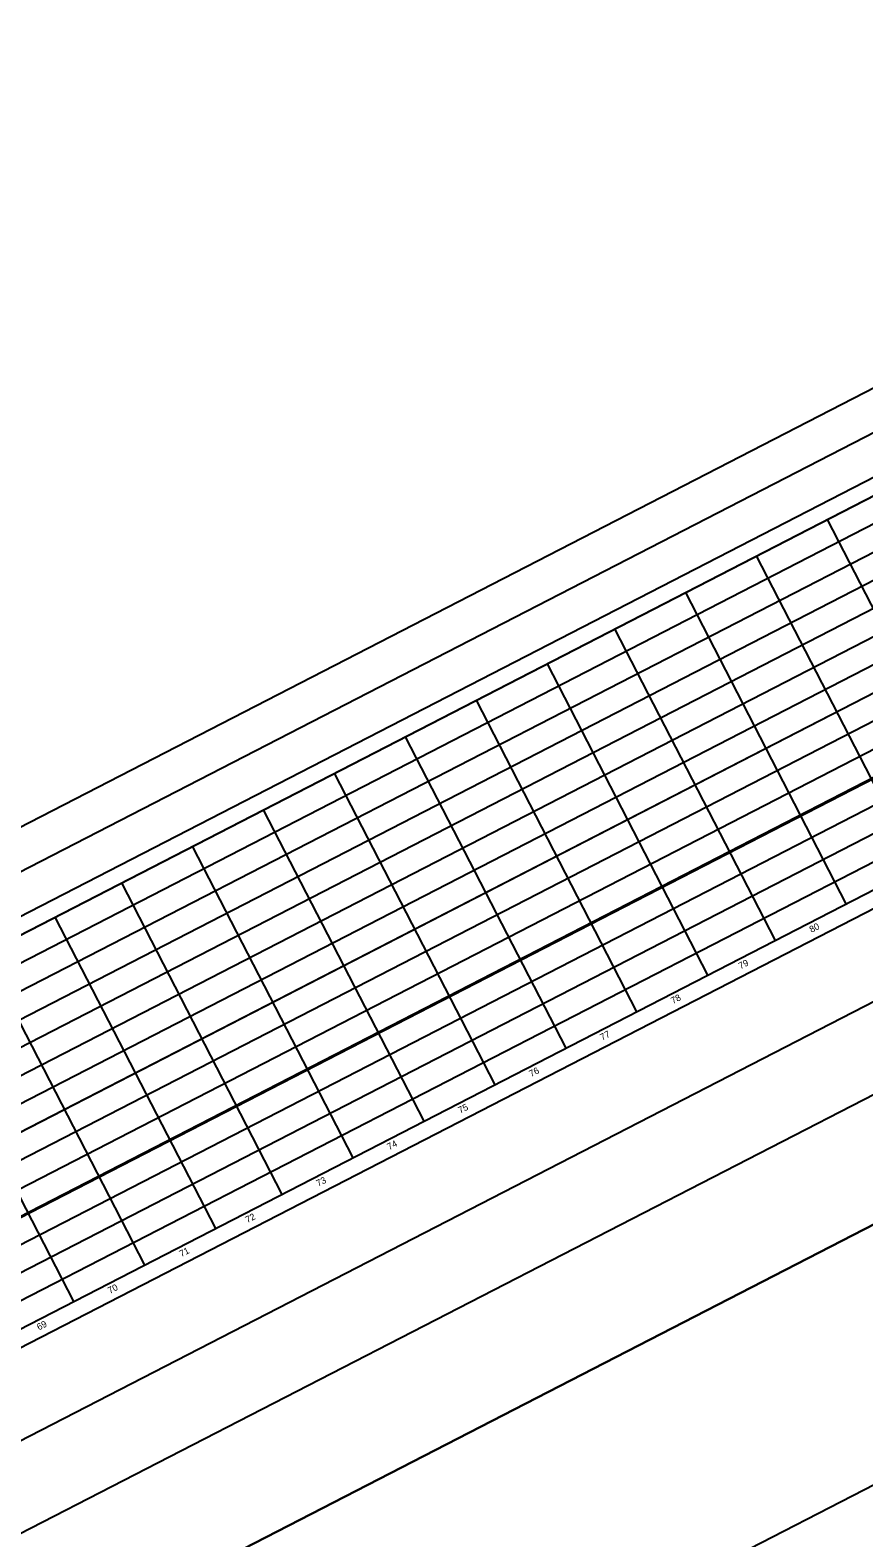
# Model space of a CAD drawing. Extents: x -886320 to -884760, y -1024172 to -1023483.
# Drawn here: x -885274.6 to -885148.6, y -1023827.5 to -1023599.4 of the extents above; entities that cross this region are included whole.
import ezdxf

# ---------------------------------------------------------------- set-up
doc = ezdxf.new("R2010")
doc.units = 0
for name, color, linetype in [('AGA__Netisknout', 7, 'Continuous'), ('Stavajici_betonova_draha', 7, 'Continuous'), ('Stavajici_betonova_draha_osa', 7, 'Continuous'), ('Stavajici_betonova_draha_Popis desky', 7, 'Continuous'), ('Stavajici_betonova_draha_Spára', 7, 'Continuous'), ('Stavajici_drahovy_system', 7, 'Continuous'), ('Stavajici_drahovy_system_osy', 7, 'Continuous'), ('Stavajici_drahovy_system_RWY_strip', 7, 'Continuous'), ('Stavajici_drahovy_system_TWY', 7, 'Continuous'), ('Stavajici_drahovy_system_TWY_osy', 7, 'Continuous')]:
    doc.layers.add(name, color=color, linetype=linetype)

msp = doc.modelspace()

# ---------------------------------------------------------------- linework, layer by layer
at = {"layer": 'AGA__Netisknout'}
msp.add_line((-886017.78, -1024147.99), (-884773.13, -1023507.02), dxfattribs=at)
at = {"layer": 'Stavajici_betonova_draha'}
for p, q in [((-886029.69, -1024124.32), (-884785.04, -1023483.35)), ((-886029.69, -1024124.32), (-884785.04, -1023483.35)), ((-886005.42, -1024171.44), (-884760.77, -1023530.47)), ((-886005.42, -1024171.44), (-884760.77, -1023530.47))]:
    msp.add_line(p, q, dxfattribs=at)
at = {"layer": 'Stavajici_betonova_draha_osa'}
msp.add_line((-886017.55, -1024147.88), (-884772.9, -1023506.91), dxfattribs=at)
at = {"layer": 'Stavajici_betonova_draha_Spára'}
for p, q in [((-886029.91, -1024124.43), (-884785.26, -1023483.46)), ((-886028.18, -1024127.8), (-884783.53, -1023486.82)), ((-886026.44, -1024131.16), (-884781.79, -1023490.19)), ((-886024.71, -1024134.53), (-884780.06, -1023493.56)), ((-886022.98, -1024137.89), (-884778.33, -1023496.92)), ((-886021.24, -1024141.26), (-884776.59, -1023500.29)), ((-886019.51, -1024144.63), (-884774.86, -1023503.65)), ((-886016.04, -1024151.36), (-884771.39, -1023510.39)), ((-886014.31, -1024154.72), (-884769.66, -1023513.75)), ((-886012.58, -1024158.09), (-884767.93, -1023517.12)), ((-886010.84, -1024161.46), (-884766.19, -1023520.48)), ((-886009.11, -1024164.82), (-884764.46, -1023523.85)), ((-886007.38, -1024168.19), (-884762.73, -1023527.21)), ((-886005.64, -1024171.55), (-884760.99, -1023530.58)), ((-885154.11, -1023673.41), (-885129.84, -1023720.53)), ((-885164.82, -1023678.92), (-885140.55, -1023726.05)), ((-885175.53, -1023684.44), (-885151.26, -1023731.56)), ((-885186.24, -1023689.96), (-885161.98, -1023737.08)), ((-885196.46, -1023695.22), (-885172.2, -1023742.34)), ((-885207.18, -1023700.74), (-885182.91, -1023747.86)), ((-885217.91, -1023706.26), (-885193.64, -1023753.39)), ((-885228.64, -1023711.79), (-885204.37, -1023758.91)), ((-885239.36, -1023717.31), (-885215.1, -1023764.44)), ((-885250.09, -1023722.84), (-885225.83, -1023769.96)), ((-885260.82, -1023728.37), (-885236.56, -1023775.49)), ((-885270.87, -1023733.54), (-885246.6, -1023780.66)), ((-885281.6, -1023739.06), (-885257.33, -1023786.19)), ((-885292.33, -1023744.59), (-885268.06, -1023791.71))]:
    msp.add_line(p, q, dxfattribs=at)
at = {"layer": 'Stavajici_drahovy_system'}
for p, q in [((-885721.56, -1024028.07), (-884864.53, -1023586.71)), ((-885726.12, -1024058.54), (-884837.08, -1023600.7)), ((-885744.78, -1024087.83), (-884802.4, -1023602.52)), ((-885728.75, -1024118.95), (-884786.38, -1023633.64))]:
    msp.add_line(p, q, dxfattribs=at)
at = {"layer": 'Stavajici_drahovy_system_osy'}
msp.add_line((-885731.84, -1024047.42), (-884842.81, -1023589.59), dxfattribs=at)
at = {"layer": 'Stavajici_drahovy_system_RWY_strip'}
for p, q in [((-885772.25, -1024034.49), (-884829.87, -1023549.18)), ((-884802.4, -1023602.52), (-885744.78, -1024087.83))]:
    msp.add_line(p, q, dxfattribs=at)
at = {"layer": 'Stavajici_drahovy_system_TWY'}
for p, q in [((-885887.27, -1024034.67), (-884885.91, -1023518.99)), ((-885748.12, -1023976.51), (-884891.09, -1023535.15))]:
    msp.add_line(p, q, dxfattribs=at)
at = {"layer": 'Stavajici_drahovy_system_TWY_osy'}
msp.add_line((-885886.7, -1024041.13), (-884883.17, -1023524.32), dxfattribs=at)

# ---------------------------------------------------------------- texts
at = {"layer": 'Stavajici_betonova_draha_Popis desky'}
for s, p in [('80', (-885156.48, -1023735.94)), ('79', (-885167.2, -1023741.46)), ('78', (-885177.42, -1023746.72)), ('77', (-885188.13, -1023752.24)), ('76', (-885198.86, -1023757.76)), ('75', (-885209.59, -1023763.29)), ('74', (-885220.32, -1023768.81)), ('73', (-885231.05, -1023774.34)), ('72', (-885241.77, -1023779.86)), ('71', (-885251.75, -1023785)), ('70', (-885262.55, -1023790.56)), ('69', (-885273.28, -1023796.09))]:
    msp.add_text(s, height=1, rotation=27.2477, dxfattribs=at).set_placement(p)

doc.saveas('drawing.dxf')
